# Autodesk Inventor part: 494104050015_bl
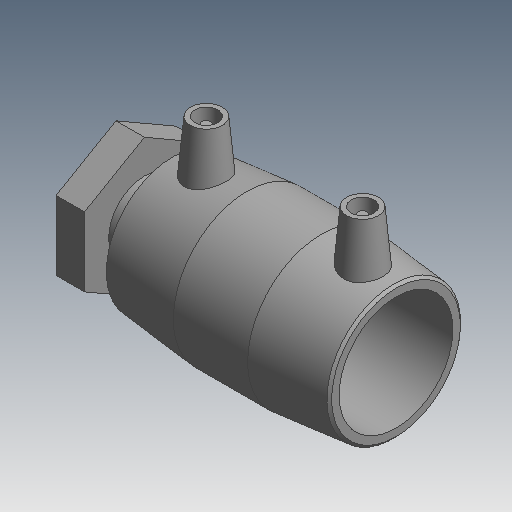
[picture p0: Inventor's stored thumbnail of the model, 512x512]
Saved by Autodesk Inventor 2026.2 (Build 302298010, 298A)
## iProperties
Created: 2017-06
Part Number: 494104050015_bl
Material: Generic
Description: PLASSON FEMALE FREE NUT TRANSITION COUPLER 50- 1½"
Document SubType Name: Modeling
Designer: KIM
Mass: 55.0731 g
Surface Area: 148.067 cm^2
Volume: 55.0731 cm^3
Density: 1 g/cm^3
Appearance: Default
Author: KIM
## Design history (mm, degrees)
derived "494104.ipt"
feature "Solid1::494104.ipt" dims "ScaleForDerivedMember" = 10
tag "TaggingFeature1"
body "Solid1"
other parameters: "d0" = 98 [user parameter], "d2" = 65 [user parameter], "d3" = 49 [user parameter], "d4" = 32.66667 [user parameter], "d5" = 58.5 [user parameter], "d6" = 47.5 [user parameter], "d29" = 52 [user parameter], "d30" = 14 [user parameter], "d31" = 34.3 [user parameter], "d34" = 5 deg [user parameter], "d41" = 4 [user parameter], "d42" = 14 [user parameter], "d43" = 0 [user parameter], "d48" = 3 [user parameter], "d49" = 0 [user parameter], "d55" = 25 [user parameter], "d80" = 1 [user parameter], "d83" = 12.5 [user parameter], "d84" = 8.25 [user parameter], "d85" = 0.825 [user parameter], "d86" = 35.876 [user parameter], "d87" = 44.845 [user parameter], "d88" = 47.845 [user parameter], "d89" = 65 [user parameter], "d96" = 31.3915 [user parameter], "d97" = 0 [user parameter], "d98" = 4.4845 [user parameter], "d99" = 4.4845 [user parameter], "d106" = 0 [user parameter], "d107" = 6.5 [user parameter], "L_" = 123 [user parameter], "L_1" = 49 [user parameter], "D_1" = 65 [user parameter], "A_" = 52 [user parameter], "d_2" = 12 [user parameter], "L_2" = 25 [user parameter], "D_" = 29 [user parameter], "G_" = 44.845 [user parameter], "d102" = 47.845 [user parameter]
